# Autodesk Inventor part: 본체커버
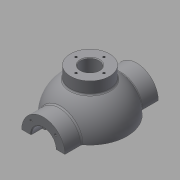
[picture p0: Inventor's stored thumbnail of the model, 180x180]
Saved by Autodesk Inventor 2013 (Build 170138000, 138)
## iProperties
Created: 2015-12
Part Number: 본체커버
Material: 일반
Document SubType Name: Modeling
Designer: mduedu
Density: 1 g/cm^3
Mass: 201.943 g
Surface Area: 428.16 cm^2
Volume: 201.943 cm^3
Author: mduedu
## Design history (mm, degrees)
sketch "스케치1"
  geometry: L1 (-53, 0)-(53, 0); A1 r 53 centre (0, 0) between (53, 0) and (-53, 0); 2 further points
  constraints: 2 coincident, 2 end point, 2 point on circle, 1 centre point, 1 horizontal, 1 midpoint
  dimensions: "d0" = 53 radius of A1
revolve "회전1" sketch "스케치1" stored, may be unused: angle "d2" = 90 deg
feature "쉘1" dims "d11" = 10
node "작업 평면1"
sketch "스케치2"
  geometry: C1 r 31 at (0, 0); 1 further point
  constraints: 1 centre point, 1 coincident
  dimensions: "d4" = 62 diameter of C1
extrude "돌출1" join sketch "스케치2" stored distance "d5" = 10; taper "d6" = 0 deg
hole "구멍1" diameter "d14" = 35; stored, may be unused: countersink angle "d18" = 90 deg, drill point angle "d20" = 0 deg; dims "d12" = 10, "d13" = 10, "d15" = 6, "d16" = 4, "d17" = 2, "d19" = 16
hole "구멍2" diameter "d23" = 27; stored, may be unused: countersink angle "d27" = 90 deg, drill point angle "d29" = 0 deg; dims "d21" = 10, "d22" = 10, "d24" = 6, "d25" = 4, "d26" = 2, "d28" = 16
fillet "모깎기1" dims "d30" = 0.3
chamfer "모따기1" distance "d40" = 1; stored, may be unused: second distance "d41" = 2, angle "d42" = 45 deg
sketch "스케치4"
  geometry: L1 (0, 0)-(0, -25); L2 (0, 0)-(-17.678, -17.678); A1 r 25 centre (0, 0) between (-17.678, -17.678) and (0, -25); 1 further point
  constraints: 4 end point, 2 point on circle, 1 centre point, 1 coincident, 1 vertical
  dimensions: "d43" = 50 diameter of A1; "d47" = 45 deg angle of L1 L2
hole "구멍4" sketch "스케치4" at (-17.678, -17.678) diameter "d49" = 3.242; stored, may be unused: countersink angle "d53" = 90 deg, drill point angle "d55" = 118 deg; dims "d50" = 11, "d51" = 4, "d52" = 2, "d54" = 13
node "작업 평면3"
sketch "스케치6"
  geometry: C1 r 65 at (0, 0); 1 further point
  constraints: 1 centre point, 1 coincident
  dimensions: "d78" = 130 diameter of C1
extrude "돌출3" join sketch "스케치6" distance "d80" = 10; taper "d81" = 0 deg
sketch "스케치7"
  geometry: C1 r 20 at (0, 0); 1 further point
  constraints: 1 centre point, 1 coincident
  dimensions: "d82" = 40 diameter of C1
extrude "돌출4" join sketch "스케치7" stored distance "d84" = 10; taper "d85" = 0 deg
sketch "스케치8"
  geometry: 2 further points
  constraints: 1 coincident
hole "구멍6" sketch "스케치8" at (0, 0) diameter "d86" = 20; stored, may be unused: countersink angle "d90" = 90 deg, drill point angle "d92" = 118 deg; dims "d87" = 7, "d88" = 40, "d89" = 5, "d91" = 10
fillet "모깎기2" dims "d93" = 0.3
sketch "스케치9"
  geometry: L1 (65, -75)-(-65, -75) reference; L2 (-45, -75)-(-38.245, -36.692); A1 r 53 centre (0, 0) between (42.988, 31) and (42.988, -31) reference; 1 further point
  constraints: 2 end point, 1 point on circle, 1 point on line
  dimensions: "d94" = 45 horizontal distance of L2.start point (0, 0); "d95" = 80 deg angle of L2 L1
feature "리브1" sketch "스케치9" dims "d96" = 1, "d97" = 8, "d98" = 0, "d99" = 0, "d100" = 1, "d101" = 1
sketch "스케치10"
  geometry: L1 (0, 0)-(0, -55); L2 (0, 0)-(-38.891, -38.891); A1 r 55 centre (0, 0) between (0, -55) and (-38.891, -38.891); 2 further points
  constraints: 4 end point, 2 coincident, 2 point on circle, 1 centre point, 1 vertical
  dimensions: "d105" = 110 diameter of A1; "d107" = 45 deg angle of L1 L2
hole "구멍7" sketch "스케치10" at (-38.891, -38.891) diameter "d109" = 10; stored, may be unused: countersink angle "d113" = 90 deg, drill point angle "d115" = 118 deg; dims "d110" = 7, "d111" = 40, "d112" = 5, "d114" = 10
fillet "모깎기3" dims "d120" = 3
fillet "모깎기4" dims "d121" = 3, "d122" = 3
fillet "모깎기5" dims "d123" = 3
fillet "모깎기6" dims "d124" = 3
sketch "스케치11"
  geometry: C1 r 5 at (-38.891, 38.891) reference; C2 r 5 at (38.891, 38.891) reference; C3 r 5 at (38.891, -38.891) reference; C4 r 5 at (-38.891, -38.891) reference; C5 r 20 at (0, 0) reference; C6 r 65 at (0, 0) reference; 1 further point
  constraints: 3 other
feature "엠보싱1" sketch "스케치11" dims "d125" = 0.5, "d126" = 0
sketch "스케치12"
  geometry: L1 (0, 100)-(0, -100); L2 (0, 100)-(-150, 100); L3 (-150, 100)-(-150, -100); L4 (-150, -100)-(0, -100); 2 further points
  constraints: 8 end point, 3 perpendicular, 1 coincident, 1 midpoint, 1 vertical
  dimensions: "d127" = 200 distance of L2.end L3.end; "d129" = 150 distance of L3.end L1.end
extrude "돌출5" cut sketch "스케치12" stored distance "d130" = 10; taper "d131" = 0 deg
node "작업 평면4"
sketch "스케치16"
  geometry: C1 r 28 at (0, 0); 1 further point
  constraints: 1 centre point, 1 coincident
  dimensions: "d148" = 56 diameter of C1
extrude "돌출9" join sketch "스케치16" stored distance "d150" = 5; taper "d151" = 0 deg
hole "구멍8" diameter "d154" = 26; stored, may be unused: countersink angle "d158" = 90 deg, drill point angle "d160" = 118 deg; dims "d152" = 10, "d153" = 10, "d155" = 6, "d156" = 4, "d157" = 2, "d159" = 8
sketch "스케치17" dims "d161" = 40
  geometry: 3 further points
  constraints: 2 vertical alignment, 1 coincident, 2 other
hole "구멍9" sketch "스케치17" at (0, 20) diameter "d163" = 3.242; stored, may be unused: countersink angle "d167" = 90 deg, drill point angle "d169" = 118 deg; dims "d164" = 8, "d165" = 4, "d166" = 2, "d168" = 10
fillet "모깎기11" dims "d173" = 3
chamfer "모따기2" distance "d174" = 1; stored, may be unused: second distance "d175" = 2, angle "d176" = 45 deg
node "솔리드1"
mirror "대칭1"
mirror "대칭2"
pattern_circular "원형 패턴1" dims angle "d57" = 360 deg
mirror "대칭3"
pattern_circular "원형 패턴3" dims angle "d103" = 360 deg
pattern_circular "원형 패턴4" dims "d40" = 1, angle "d118" = 360 deg
pattern_circular "원형 패턴5" dims angle "d171" = 360 deg
node "투영된 루프1"
other parameters: "d3" = 67, "d77" = -85, "d147" = 62
